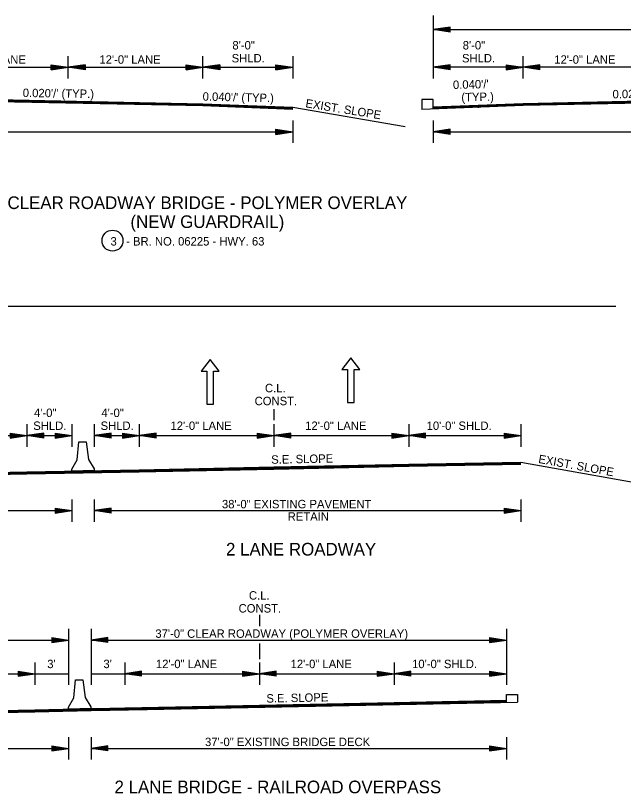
# Model space of a CAD drawing. Extents: x 545241 to 1930787, y -1971772 to 596640.
# Drawn here: x 547199 to 547741, y -1949540 to -1948847 of the extents above; entities that cross this region are included whole.
import ezdxf

# ---------------------------------------------------------------- set-up
doc = ezdxf.new("R2010")
doc.units = 0
for name, color, linetype in [('Default', 7, 'Continuous'), ('R_Border', 7, 'Continuous'), ('R_Draft', 7, 'Continuous')]:
    doc.layers.add(name, color=color, linetype=linetype)

# ---------------------------------------------------------------- blocks, each defined once
blk = doc.blocks.new('ARROW')
at = {"layer": 'R_Draft'}
for p, q in [((-2, 0.3), (0, 0)), ((-2, 0.3), (-2, -0.3)), ((-2, 0.25), (-0.334, 0)), ((-2, 0.199), (-0.678, 0)), ((-2, 0.149), (-1.011, 0)), ((-2, 0.097), (-1.35, 0)), ((-2, 0.047), (-1.684, 0)), ((-2, -0.3), (0, 0)), ((-2, -0.098), (-1.35, 0)), ((-2, -0.199), (-0.678, 0)), ((-2, -0.25), (-0.334, 0)), ((-2, -0.149), (-1.011, 0)), ((-2, -0.047), (-1.684, 0))]:
    blk.add_line(p, q, dxfattribs=at)
blk = doc.blocks.new('MedBarrier')
at = {"layer": 'Default'}
blk.add_lwpolyline([(-9.99, 0), (-9.91, 1.67), (-4.99, 10), (-3.32, 25.83), (3.32, 25.83), (4.99, 10), (9.91, 1.67), (9.99, 0)], close=True, dxfattribs=at)

msp = doc.modelspace()

# ---------------------------------------------------------------- linework, layer by layer
at = {"layer": 'R_Border'}
for p, q in [((547561.01, -1948921.93), (547561, -1948931.06)), ((547571.18, -1948921.93), (547561.01, -1948921.93)), ((547571.18, -1948930.57), (547571.18, -1948921.93)), ((546887.2, -1949106.18), (547733.92, -1949106.18)), ((547429.31, -1949197.63), (547429.31, -1949207.63)), ((547209.31, -1949211.23), (547209.31, -1949231.23)), ((547249.31, -1949211.23), (547249.31, -1949231.23)), ((547269.31, -1949211.23), (547269.31, -1949231.23)), ((547309.31, -1949211.23), (547309.31, -1949231.23)), ((547429.31, -1949211.23), (547429.31, -1949231.23)), ((547549.31, -1949211.23), (547549.31, -1949231.23)), ((547649.31, -1949211.23), (547649.31, -1949231.23)), ((546869.31, -1949221.23), (547249.31, -1949221.23)), ((547269.31, -1949221.23), (547649.31, -1949221.23)), ((547649.31, -1949244.83), (547749.31, -1949262.83)), ((547249.31, -1949278.03), (547249.31, -1949298.03)), ((547269.31, -1949278.03), (547269.31, -1949298.03)), ((547649.31, -1949278.03), (547649.31, -1949298.03)), ((546869.31, -1949288.03), (547249.31, -1949288.03)), ((547269.31, -1949288.03), (547649.31, -1949288.03)), ((547416.35, -1949380.81), (547416.35, -1949390.81)), ((547246.35, -1949393.31), (547246.35, -1949443.31)), ((547266.35, -1949393.31), (547266.35, -1949443.31)), ((547636.35, -1949393.31), (547636.35, -1949443.31)), ((546876.35, -1949403.31), (547246.35, -1949403.31)), ((547266.35, -1949403.31), (547636.35, -1949403.31)), ((547416.35, -1949406.31), (547416.35, -1949420.31)), ((547216.35, -1949423.31), (547216.35, -1949443.31)), ((547296.35, -1949423.31), (547296.35, -1949443.31)), ((547416.35, -1949423.31), (547416.35, -1949443.31)), ((547536.35, -1949423.31), (547536.35, -1949443.31)), ((546876.35, -1949433.31), (547246.35, -1949433.31)), ((547266.35, -1949433.31), (547636.35, -1949433.31)), ((547246.35, -1949489.71), (547246.35, -1949509.71)), ((547266.35, -1949489.71), (547266.35, -1949509.71)), ((547636.35, -1949489.71), (547636.35, -1949509.71)), ((546876.35, -1949499.71), (547246.35, -1949499.71)), ((547266.35, -1949499.71), (547636.35, -1949499.71))]:
    msp.add_line(p, q, dxfattribs=at)
for points in [[(547380.54, -1949163.92), (547372.54, -1949153.53), (547364.54, -1949163.92), (547369.54, -1949163.92), (547369.54, -1949193.34), (547375.54, -1949193.34), (547375.54, -1949163.92)], [(547505.8, -1949162.4), (547497.8, -1949152.01), (547489.8, -1949162.4), (547494.8, -1949162.4), (547494.8, -1949191.82), (547500.8, -1949191.82), (547500.8, -1949162.4)]]:
    msp.add_lwpolyline(points, close=True, dxfattribs=at)
for points in [[(547259.31, -1949252.63), (547309.31, -1949251.63), (547429.31, -1949249.23), (547549.31, -1949246.83), (547649.31, -1949244.83)], [(547259.31, -1949252.93), (547309.31, -1949251.93), (547429.31, -1949249.53), (547549.31, -1949247.13), (547649.31, -1949245.13)], [(547259.31, -1949253.23), (547309.31, -1949252.23), (547429.31, -1949249.83), (547549.31, -1949247.43), (547649.31, -1949245.43)], [(547259.31, -1949253.53), (547309.31, -1949252.53), (547429.31, -1949250.13), (547549.31, -1949247.73), (547649.31, -1949245.73)], [(547259.31, -1949253.83), (547309.31, -1949252.83), (547429.31, -1949250.43), (547549.31, -1949248.03), (547649.31, -1949246.03)], [(547259.31, -1949254.13), (547309.31, -1949253.13), (547429.31, -1949250.73), (547549.31, -1949248.33), (547649.31, -1949246.33)], [(547259.31, -1949254.43), (547309.31, -1949253.43), (547429.31, -1949251.03), (547549.31, -1949248.63), (547649.31, -1949246.63)], [(546869.31, -1949260.43), (546969.31, -1949258.43), (547089.31, -1949256.03), (547209.31, -1949253.63), (547259.31, -1949252.63)], [(546869.31, -1949260.73), (546969.31, -1949258.73), (547089.31, -1949256.33), (547209.31, -1949253.93), (547259.31, -1949252.93)], [(546869.31, -1949261.03), (546969.31, -1949259.03), (547089.31, -1949256.63), (547209.31, -1949254.23), (547259.31, -1949253.23)], [(546869.31, -1949261.33), (546969.31, -1949259.33), (547089.31, -1949256.93), (547209.31, -1949254.53), (547259.31, -1949253.53)], [(546869.31, -1949261.63), (546969.31, -1949259.63), (547089.31, -1949257.23), (547209.31, -1949254.83), (547259.31, -1949253.83)], [(546869.31, -1949261.93), (546969.31, -1949259.93), (547089.31, -1949257.53), (547209.31, -1949255.13), (547259.31, -1949254.13)], [(546869.31, -1949262.23), (546969.31, -1949260.23), (547089.31, -1949257.83), (547209.31, -1949255.43), (547259.31, -1949254.43)], [(547636.35, -1949458.41), (547636.35, -1949451.81), (547646.35, -1949451.81), (547646.35, -1949458.51)], [(547256.35, -1949464.51), (547296.35, -1949463.71), (547416.35, -1949461.31), (547536.35, -1949458.91), (547636.35, -1949456.91)], [(547256.35, -1949464.81), (547296.35, -1949464.01), (547416.35, -1949461.61), (547536.35, -1949459.21), (547636.35, -1949457.21)], [(547256.35, -1949465.11), (547296.35, -1949464.31), (547416.35, -1949461.91), (547536.35, -1949459.51), (547636.35, -1949457.51)], [(547256.35, -1949465.41), (547296.35, -1949464.61), (547416.35, -1949462.21), (547536.35, -1949459.81), (547636.35, -1949457.81)], [(547256.35, -1949465.71), (547296.35, -1949464.91), (547416.35, -1949462.51), (547536.35, -1949460.11), (547636.35, -1949458.11)], [(547256.35, -1949466.01), (547296.35, -1949465.21), (547416.35, -1949462.81), (547536.35, -1949460.41), (547636.35, -1949458.41)], [(547266.35, -1949464.31), (547316.35, -1949463.31), (547436.35, -1949460.91), (547556.35, -1949458.51), (547636.35, -1949456.91)], [(547266.35, -1949464.61), (547316.35, -1949463.61), (547436.35, -1949461.21), (547556.35, -1949458.81), (547636.35, -1949457.21)], [(547266.35, -1949464.91), (547316.35, -1949463.91), (547436.35, -1949461.51), (547556.35, -1949459.11), (547636.35, -1949457.51)], [(547266.35, -1949465.21), (547316.35, -1949464.21), (547436.35, -1949461.81), (547556.35, -1949459.41), (547636.35, -1949457.81)], [(547266.35, -1949465.51), (547316.35, -1949464.51), (547436.35, -1949462.11), (547556.35, -1949459.71), (547636.35, -1949458.11)], [(547266.35, -1949465.81), (547316.35, -1949464.81), (547436.35, -1949462.41), (547556.35, -1949460.01), (547636.35, -1949458.41)], [(547266.35, -1949466.11), (547316.35, -1949465.11), (547436.35, -1949462.71), (547556.35, -1949460.31), (547646.35, -1949458.51)], [(546866.35, -1949474.11), (546976.35, -1949471.91), (547096.35, -1949469.51), (547216.35, -1949467.11), (547266.35, -1949466.11)], [(546876.35, -1949472.11), (546976.35, -1949470.11), (547096.35, -1949467.71), (547216.35, -1949465.31), (547266.35, -1949464.31)], [(546876.35, -1949472.41), (546976.35, -1949470.41), (547096.35, -1949468.01), (547216.35, -1949465.61), (547266.35, -1949464.61)], [(546876.35, -1949472.71), (546976.35, -1949470.71), (547096.35, -1949468.31), (547216.35, -1949465.91), (547266.35, -1949464.91)], [(546876.35, -1949473.01), (546976.35, -1949471.01), (547096.35, -1949468.61), (547216.35, -1949466.21), (547266.35, -1949465.21)], [(546876.35, -1949473.31), (546976.35, -1949471.31), (547096.35, -1949468.91), (547216.35, -1949466.51), (547266.35, -1949465.51)], [(546876.35, -1949473.61), (546976.35, -1949471.61), (547096.35, -1949469.21), (547216.35, -1949466.81), (547266.35, -1949465.81)]]:
    msp.add_lwpolyline(points, dxfattribs=at)
msp.add_circle((547285.51, -1949047.71), 9.34, dxfattribs=at)
at = {"layer": 'R_Draft'}
for p, q in [((547571.15, -1948847.31), (547571.15, -1948903.38)), ((547586.15, -1948857.59), (547571.15, -1948859.84)), ((547586.15, -1948857.97), (547573.66, -1948859.84)), ((547586.15, -1948858.35), (547576.24, -1948859.84)), ((547586.15, -1948858.73), (547578.74, -1948859.84)), ((547586.15, -1948859.11), (547581.28, -1948859.84)), ((547586.15, -1948859.49), (547583.78, -1948859.84)), ((547586.15, -1948862.09), (547586.15, -1948857.59)), ((547571.15, -1948859.84), (548211.15, -1948859.84)), ((547586.15, -1948862.09), (547571.15, -1948859.84)), ((547586.15, -1948861.72), (547573.66, -1948859.84)), ((547586.15, -1948861.34), (547576.24, -1948859.84)), ((547586.15, -1948860.96), (547578.74, -1948859.84)), ((547586.15, -1948860.57), (547581.28, -1948859.84)), ((547586.15, -1948860.2), (547583.78, -1948859.84)), ((547246.01, -1948903.38), (547246.01, -1948883.49)), ((547366.01, -1948903.38), (547366.01, -1948883.49)), ((547446.01, -1948883.38), (547446.01, -1948903.38)), ((547651.15, -1948903.38), (547651.15, -1948883.49)), ((547126.01, -1948893.38), (547246.01, -1948893.38)), ((547231.01, -1948891.13), (547246.01, -1948893.38)), ((547231.01, -1948895.63), (547231.01, -1948891.13)), ((547231.01, -1948891.51), (547243.51, -1948893.38)), ((547231.01, -1948891.89), (547240.93, -1948893.38)), ((547231.01, -1948892.26), (547238.43, -1948893.38)), ((547231.01, -1948892.65), (547235.89, -1948893.38)), ((547231.01, -1948893.03), (547233.38, -1948893.38)), ((547231.01, -1948895.63), (547246.01, -1948893.38)), ((547231.01, -1948894.11), (547235.89, -1948893.38)), ((547231.01, -1948894.87), (547240.93, -1948893.38)), ((547231.01, -1948895.26), (547243.51, -1948893.38)), ((547231.01, -1948894.5), (547238.43, -1948893.38)), ((547231.01, -1948893.73), (547233.38, -1948893.38)), ((547261.01, -1948891.13), (547246.01, -1948893.38)), ((547261.01, -1948895.63), (547246.01, -1948893.38)), ((547246.01, -1948893.38), (547366.01, -1948893.38)), ((547261.01, -1948891.51), (547248.52, -1948893.38)), ((547261.01, -1948895.26), (547248.52, -1948893.38)), ((547261.01, -1948891.89), (547251.1, -1948893.38)), ((547261.01, -1948894.87), (547251.1, -1948893.38)), ((547261.01, -1948892.26), (547253.59, -1948893.38)), ((547261.01, -1948894.5), (547253.59, -1948893.38)), ((547261.01, -1948892.65), (547256.14, -1948893.38)), ((547261.01, -1948894.12), (547256.14, -1948893.38)), ((547261.01, -1948893.03), (547258.64, -1948893.38)), ((547261.01, -1948893.73), (547258.64, -1948893.38)), ((547261.01, -1948891.13), (547261.01, -1948895.63)), ((547351.01, -1948891.13), (547366.01, -1948893.38)), ((547351.01, -1948895.63), (547351.01, -1948891.13)), ((547351.01, -1948891.51), (547363.51, -1948893.38)), ((547351.01, -1948891.89), (547360.93, -1948893.38)), ((547351.01, -1948892.26), (547358.43, -1948893.38)), ((547351.01, -1948892.65), (547355.89, -1948893.38)), ((547351.01, -1948893.03), (547353.38, -1948893.38)), ((547351.01, -1948895.63), (547366.01, -1948893.38)), ((547351.01, -1948894.11), (547355.89, -1948893.38)), ((547351.01, -1948894.87), (547360.93, -1948893.38)), ((547351.01, -1948895.26), (547363.51, -1948893.38)), ((547351.01, -1948894.5), (547358.43, -1948893.38)), ((547351.01, -1948893.73), (547353.38, -1948893.38)), ((547381.01, -1948891.13), (547366.01, -1948893.38)), ((547366.01, -1948893.38), (547446.01, -1948893.38)), ((547381.01, -1948895.63), (547366.01, -1948893.38)), ((547381.01, -1948891.51), (547368.52, -1948893.38)), ((547381.01, -1948895.26), (547368.52, -1948893.38)), ((547381.01, -1948891.89), (547371.1, -1948893.38)), ((547381.01, -1948894.87), (547371.1, -1948893.38)), ((547381.01, -1948892.26), (547373.59, -1948893.38)), ((547381.01, -1948894.5), (547373.59, -1948893.38)), ((547381.01, -1948892.65), (547376.14, -1948893.38)), ((547381.01, -1948894.12), (547376.14, -1948893.38)), ((547381.01, -1948893.03), (547378.64, -1948893.38)), ((547381.01, -1948893.73), (547378.64, -1948893.38)), ((547381.01, -1948891.13), (547381.01, -1948895.63)), ((547431.01, -1948891.13), (547446.01, -1948893.38)), ((547431.01, -1948895.63), (547431.01, -1948891.13)), ((547431.01, -1948891.51), (547443.51, -1948893.38)), ((547431.01, -1948891.89), (547440.93, -1948893.38)), ((547431.01, -1948892.26), (547438.43, -1948893.38)), ((547431.01, -1948892.65), (547435.89, -1948893.38)), ((547431.01, -1948893.03), (547433.38, -1948893.38)), ((547431.01, -1948895.63), (547446.01, -1948893.38)), ((547431.01, -1948894.11), (547435.89, -1948893.38)), ((547431.01, -1948894.87), (547440.93, -1948893.38)), ((547431.01, -1948895.26), (547443.51, -1948893.38)), ((547431.01, -1948894.5), (547438.43, -1948893.38)), ((547431.01, -1948893.73), (547433.38, -1948893.38)), ((547586.15, -1948891.13), (547571.15, -1948893.38)), ((547651.15, -1948893.38), (547571.15, -1948893.38)), ((547586.15, -1948895.63), (547571.15, -1948893.38)), ((547586.15, -1948891.51), (547573.66, -1948893.38)), ((547586.15, -1948895.26), (547573.66, -1948893.38)), ((547586.15, -1948891.89), (547576.24, -1948893.38)), ((547586.15, -1948894.87), (547576.24, -1948893.38)), ((547586.15, -1948892.26), (547578.74, -1948893.38)), ((547586.15, -1948894.5), (547578.74, -1948893.38)), ((547586.15, -1948892.65), (547581.28, -1948893.38)), ((547586.15, -1948894.11), (547581.28, -1948893.38)), ((547586.15, -1948893.03), (547583.78, -1948893.38)), ((547586.15, -1948893.73), (547583.78, -1948893.38)), ((547586.15, -1948895.63), (547586.15, -1948891.13)), ((547636.15, -1948891.13), (547651.15, -1948893.38)), ((547636.15, -1948891.13), (547636.15, -1948895.63)), ((547636.15, -1948891.51), (547648.65, -1948893.38)), ((547636.15, -1948891.89), (547646.07, -1948893.38)), ((547636.15, -1948892.26), (547643.57, -1948893.38)), ((547636.15, -1948892.65), (547641.03, -1948893.38)), ((547636.15, -1948893.03), (547638.52, -1948893.38)), ((547636.15, -1948895.63), (547651.15, -1948893.38)), ((547636.15, -1948894.12), (547641.03, -1948893.38)), ((547636.15, -1948894.87), (547646.07, -1948893.38)), ((547636.15, -1948895.26), (547648.65, -1948893.38)), ((547636.15, -1948894.5), (547643.57, -1948893.38)), ((547636.15, -1948893.73), (547638.52, -1948893.38)), ((547666.15, -1948891.13), (547651.15, -1948893.38)), ((547771.15, -1948893.38), (547651.15, -1948893.38)), ((547666.15, -1948895.63), (547651.15, -1948893.38)), ((547666.15, -1948891.51), (547653.66, -1948893.38)), ((547666.15, -1948895.26), (547653.66, -1948893.38)), ((547666.15, -1948891.89), (547656.24, -1948893.38)), ((547666.15, -1948894.87), (547656.24, -1948893.38)), ((547666.15, -1948892.26), (547658.74, -1948893.38)), ((547666.15, -1948894.5), (547658.74, -1948893.38)), ((547666.15, -1948892.65), (547661.28, -1948893.38)), ((547666.15, -1948894.11), (547661.28, -1948893.38)), ((547666.15, -1948893.03), (547663.78, -1948893.38)), ((547666.15, -1948893.73), (547663.78, -1948893.38)), ((547666.15, -1948895.63), (547666.15, -1948891.13)), ((547125.99, -1948921.89), (547366.01, -1948926.69)), ((547126, -1948921.29), (547366.01, -1948926.09)), ((547126, -1948921.59), (547366.01, -1948926.39)), ((547126.01, -1948920.99), (547366.01, -1948925.79)), ((547891.15, -1948920.99), (547651.15, -1948925.79)), ((547891.16, -1948921.29), (547651.15, -1948926.09)), ((547891.17, -1948921.59), (547651.15, -1948926.39)), ((547891.17, -1948921.89), (547651.15, -1948926.69)), ((547125.98, -1948922.49), (547366.01, -1948927.29)), ((547125.98, -1948922.66), (547366.01, -1948927.46)), ((547125.99, -1948922.19), (547366.01, -1948926.99)), ((547366.01, -1948925.79), (547446.01, -1948928.99)), ((547366.01, -1948926.09), (547446.01, -1948929.29)), ((547366.01, -1948926.39), (547446.01, -1948929.59)), ((547366.01, -1948926.69), (547446.01, -1948929.89)), ((547366.01, -1948926.99), (547446.01, -1948930.19)), ((547366.01, -1948927.29), (547446.01, -1948930.49)), ((547366.01, -1948927.46), (547446.01, -1948930.66)), ((547406.01, -1948927.79), (547406.01, -1948929.46)), ((547651.15, -1948927.46), (547561, -1948931.06)), ((547651.15, -1948925.79), (547571.15, -1948928.99)), ((547651.15, -1948926.09), (547571.15, -1948929.29)), ((547651.15, -1948926.39), (547571.15, -1948929.59)), ((547651.15, -1948926.69), (547571.15, -1948929.89)), ((547651.15, -1948926.99), (547571.15, -1948930.19)), ((547651.15, -1948927.29), (547571.15, -1948930.49)), ((547611.15, -1948927.79), (547611.15, -1948929.46)), ((547891.18, -1948922.19), (547651.15, -1948926.99)), ((547891.18, -1948922.49), (547651.15, -1948927.29)), ((547891.19, -1948922.66), (547651.15, -1948927.46)), ((547446.01, -1948928.99), (547546.05, -1948945.95)), ((547446.01, -1948940.6), (547446.01, -1948960.6)), ((547571.15, -1948940.6), (547571.15, -1948960.6)), ((547431.01, -1948948.6), (547446.01, -1948950.85)), ((547431.01, -1948953.1), (547431.01, -1948948.6)), ((547431.01, -1948948.97), (547443.51, -1948950.85)), ((547431.01, -1948949.35), (547440.93, -1948950.85)), ((547586.15, -1948948.6), (547571.15, -1948950.85)), ((547586.15, -1948948.97), (547573.66, -1948950.85)), ((547586.15, -1948949.35), (547576.24, -1948950.85)), ((547586.15, -1948953.1), (547586.15, -1948948.6)), ((546806.01, -1948950.85), (547446.01, -1948950.93)), ((547431.01, -1948949.73), (547438.43, -1948950.85)), ((547431.01, -1948950.11), (547435.89, -1948950.85)), ((547431.01, -1948950.49), (547433.38, -1948950.85)), ((547431.01, -1948953.1), (547446.01, -1948950.85)), ((547431.01, -1948951.57), (547435.89, -1948950.85)), ((547431.01, -1948952.34), (547440.93, -1948950.85)), ((547431.01, -1948952.72), (547443.51, -1948950.85)), ((547431.01, -1948951.96), (547438.43, -1948950.85)), ((547431.01, -1948951.2), (547433.38, -1948950.85)), ((547571.15, -1948950.85), (548211.15, -1948950.93)), ((547586.15, -1948953.1), (547571.15, -1948950.85)), ((547586.15, -1948952.72), (547573.66, -1948950.85)), ((547586.15, -1948952.34), (547576.24, -1948950.85)), ((547586.15, -1948949.73), (547578.74, -1948950.85)), ((547586.15, -1948951.96), (547578.74, -1948950.85)), ((547586.15, -1948950.11), (547581.28, -1948950.85)), ((547586.15, -1948951.57), (547581.28, -1948950.85)), ((547586.15, -1948950.49), (547583.78, -1948950.85)), ((547586.15, -1948951.2), (547583.78, -1948950.85))]:
    msp.add_line(p, q, dxfattribs=at)

# ---------------------------------------------------------------- block references
at = {"layer": 'R_Border', "xscale": 7.5, "yscale": 7.5}
for p in [(547209.31, -1949221.23), (547249.31, -1949221.23), (547309.31, -1949221.23), (547429.31, -1949221.23), (547549.31, -1949221.23), (547649.31, -1949221.23), (547249.31, -1949288.03), (547649.31, -1949288.03), (547246.35, -1949403.31), (547636.35, -1949403.31), (547216.35, -1949433.31), (547416.35, -1949433.31), (547536.35, -1949433.31), (547636.35, -1949433.31), (547246.35, -1949499.71), (547636.35, -1949499.71)]:
    msp.add_blockref('ARROW', p, dxfattribs=at)
at = {"layer": 'R_Border', "xscale": 7.5, "yscale": 7.5, "rotation": 180}
for p in [(547209.31, -1949221.23), (547269.31, -1949221.23), (547309.31, -1949221.23), (547429.31, -1949221.23), (547549.31, -1949221.23), (547269.31, -1949288.03), (547266.35, -1949403.31), (547296.35, -1949433.31), (547416.35, -1949433.31), (547536.35, -1949433.31), (547266.35, -1949499.71)]:
    msp.add_blockref('ARROW', p, dxfattribs=at)
at = {"layer": 'R_Draft', "rotation": 1.1462733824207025}
for p in [(547259.31, -1949252.63), (547256.35, -1949464.51)]:
    msp.add_blockref('MedBarrier', p, dxfattribs=at)

# ---------------------------------------------------------------- texts
at = {"layer": 'R_Border'}
for s, height, p in [('C.L.', 7.5, (547421.28, -1949182.71)), ('CONST.', 7.5, (547412.07, -1949194.21)), ('4\'-0"', 7.5, (547215.58, -1949204.73)), ('4\'-0"', 7.5, (547275.58, -1949204.73)), ('SHLD.', 7.5, (547214.9, -1949216.23)), ('SHLD.', 7.5, (547274.9, -1949216.23)), ('12\'-0" LANE', 7.5, (547337.13, -1949216.23)), ('12\'-0" LANE', 7.5, (547457.13, -1949216.23)), ('10\'-0" SHLD.', 7.5, (547565.3, -1949216.23)), ('38\'-0" EXISTING PAVEMENT', 7.5, (547382.99, -1949286.03)), ('RETAIN', 7.5, (547441.51, -1949297.03)), ('2 LANE ROADWAY', 11.25, (547386.59, -1949328.03)), ('C.L.', 7.5, (547407.02, -1949367.31)), ('CONST.', 7.5, (547397.8, -1949378.81)), ('37\'-0" CLEAR ROADWAY (POLYMER OVERLAY)', 7.5, (547323.67, -1949401.31)), ("3'", 7.5, (547227.39, -1949428.31)), ("3'", 7.5, (547277.39, -1949428.31)), ('12\'-0" LANE', 7.5, (547324.16, -1949428.31)), ('12\'-0" LANE', 7.5, (547444.16, -1949428.31)), ('10\'-0" SHLD.', 7.5, (547552.33, -1949428.31)), ('37\'-0" EXISTING BRIDGE DECK', 7.5, (547367.9, -1949497.71)), ('2 LANE BRIDGE - RAILROAD OVERPASS', 11.25, (547287.29, -1949539.71))]:
    msp.add_text(s, height=height, dxfattribs=at).set_placement(p)
for s, rotation, p in [('S.E. SLOPE', 1.1458, (547426.93, -1949246.4)), ('EXIST. SLOPE', 349.796, (547664.38, -1949245.54)), ('S.E. SLOPE', 1.1458, (547422.61, -1949459.02))]:
    msp.add_text(s, height=7.5, rotation=rotation, dxfattribs=at).set_placement(p)
at = {"layer": 'R_Draft'}
for s, height, p in [('8\'-0" ', 7.5, (547392.28, -1948877.52)), ('8\'-0" ', 7.5, (547597.42, -1948877.52)), ('12\'-0" LANE', 7.5, (547153.83, -1948890.21)), ('12\'-0" LANE', 7.5, (547273.83, -1948890.21)), ('SHLD.', 7.5, (547391.6, -1948889.02)), ('SHLD.', 7.5, (547596.74, -1948889.02)), ('12\'-0" LANE', 7.5, (547678.97, -1948890.21)), ('64 FT. CLEAR ROADWAY BRIDGE - POLYMER OVERLAY', 11.25, (547144.31, -1949019.56)), ('(NEW GUARDRAIL)', 11.25, (547301.46, -1949036.43)), ('3   - BR. NO. 06225 - HWY. 63', 7.5, (547283.71, -1949052.06))]:
    msp.add_text(s, height=height, dxfattribs=at).set_placement(p)
for s, rotation, p in [("0.040'/' ", 1.31838, (547588.81, -1948912.7)), ("0.020'/' (TYP.)", 359.12809, (547205.51, -1948919.82)), ("0.020'/' (TYP.)", 0.87191, (547730.88, -1948921.05)), ("0.040'/' (TYP.)", 358.68162, (547365.71, -1948923.04)), ('EXIST. SLOPE', 350.84656, (547456.98, -1948928.9)), ('(TYP.)', 1.31838, (547596.27, -1948923.78))]:
    msp.add_text(s, height=7.5, rotation=rotation, dxfattribs=at).set_placement(p)

doc.saveas('drawing.dxf')
